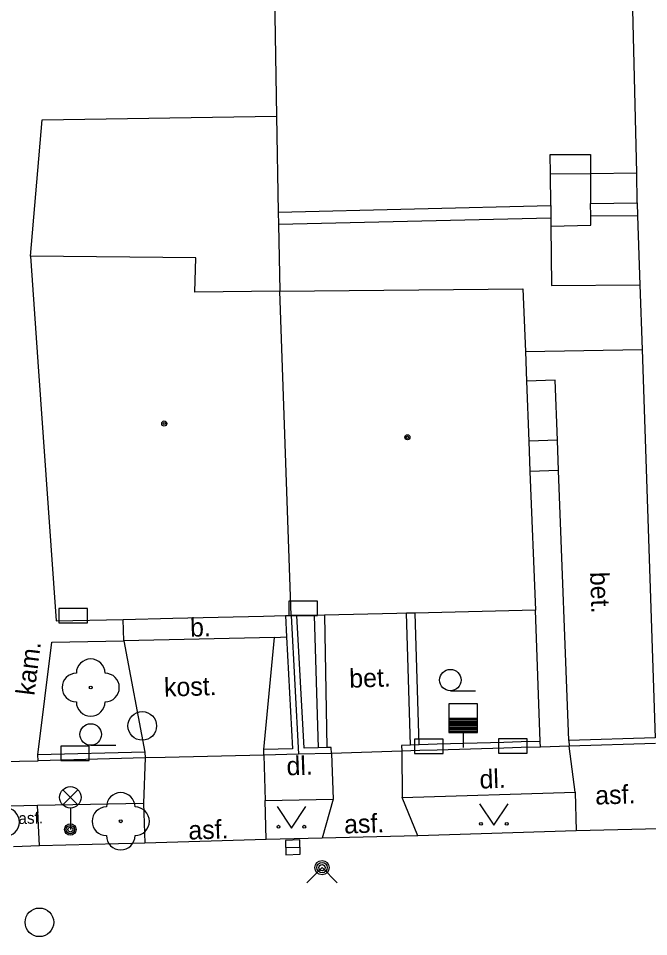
# Model space of a CAD drawing. Extents: x -595546 to -593986, y -1160845 to -1159202.
# Drawn here: x -595096.78 to -595074.76, y -1160780.82 to -1160748.75 of the extents above; entities that cross this region are included whole.
import ezdxf

# ---------------------------------------------------------------- set-up
doc = ezdxf.new("R2010")
doc.units = 0
for name, color, linetype in [('DOP - kresba z DSPS bez souradnic', 7, 'Continuous'), ('DOP - rozhrani ploch obecne', 7, 'Continuous'), ('Level 22', 7, 'Continuous'), ('Level 24', 7, 'Continuous'), ('Level 27', 7, 'Continuous'), ('Level 28', 7, 'Continuous'), ('Level 31', 7, 'Continuous'), ('Level 33', 7, 'Continuous'), ('Level 36', 7, 'Continuous'), ('Level 39', 7, 'Continuous'), ('Specificka linie pasportu komunikaci', 7, 'Continuous'), ('TM - budovy zdene_ betonove - VP', 7, 'Continuous'), ('TM - chodniky - VP', 7, 'Continuous'), ('TM - komunikace - VP', 7, 'Continuous'), ('TM - letecke snimky - pomocna linie', 7, 'Continuous'), ('TM - plot drateny_ kovovy - VP', 7, 'Continuous'), ('TM - podezdivka plotu - VP', 7, 'Continuous'), ('TM - popis povrchu', 7, 'Continuous'), ('TM - rozhrani mezi zpev. plochami mezi sebou - VP', 7, 'Continuous'), ('TM - rozhrani ploch obecne - VP', 7, 'Continuous'), ('TM - vjezd na pozemek', 7, 'Continuous'), ('TM - zed operna - VP', 7, 'Continuous')]:
    doc.layers.add(name, color=color, linetype=linetype)

msp = doc.modelspace()

# ---------------------------------------------------------------- linework, layer by layer
at = {"layer": 'DOP - kresba z DSPS bez souradnic'}
for points in [[(-595078.18, -1160755.29), (-595078.18, -1160755.72)], [(-595076.78, -1160755.66), (-595076.79, -1160755.22)], [(-595075.15, -1160755.65), (-595076.78, -1160755.66)], [(-595076.78, -1160755.97), (-595076.78, -1160755.66)], [(-595087.69, -1160755.94), (-595078.18, -1160755.72)], [(-595078.18, -1160755.72), (-595078.18, -1160756.01)], [(-595078.18, -1160756.01), (-595076.78, -1160755.97)]]:
    msp.add_lwpolyline(points, dxfattribs=at)
at = {"layer": 'DOP - rozhrani ploch obecne'}
for points in [[(-595088.03, -1160735.99), (-595087.76, -1160752.17)], [(-595075.18, -1160754.15), (-595075.54, -1160739.39)], [(-595087.76, -1160752.17), (-595087.7, -1160755.52)], [(-595078.2, -1160753.51), (-595076.8, -1160753.5)], [(-595078.19, -1160754.18), (-595078.2, -1160753.51)], [(-595076.8, -1160753.5), (-595076.8, -1160754.17)], [(-595078.18, -1160755.29), (-595078.19, -1160754.18)], [(-595076.8, -1160754.17), (-595076.79, -1160755.22)], [(-595075.16, -1160755.19), (-595075.18, -1160754.15)], [(-595087.7, -1160755.52), (-595078.18, -1160755.29)], [(-595076.79, -1160755.22), (-595075.16, -1160755.19)], [(-595075.16, -1160755.19), (-595075.15, -1160755.65)], [(-595087.7, -1160755.52), (-595087.69, -1160755.94)], [(-595075.15, -1160755.65), (-595075.07, -1160758.06)], [(-595087.69, -1160755.94), (-595087.64, -1160758.28)], [(-595075.07, -1160758.06), (-595074.99, -1160760.31)]]:
    msp.add_lwpolyline(points, dxfattribs=at)
at = {"layer": 'Level 22'}
for centre in [(-595094.25, -1160772.12), (-595093.2, -1160776.79)]:
    msp.add_circle(centre, 0.05, dxfattribs=at)
for centre, start, end in [((-595094.25, -1160771.62), 0, 180), ((-595094.75, -1160772.12), 90, 270), ((-595093.75, -1160772.12), 270, 90), ((-595094.25, -1160772.62), 180, 0), ((-595093.2, -1160776.29), 0, 180), ((-595097.24, -1160776.82), 270, 90), ((-595093.7, -1160776.79), 90, 270), ((-595092.7, -1160776.79), 270, 90), ((-595093.2, -1160777.29), 180, 0)]:
    msp.add_arc(centre, 0.5, start, end, dxfattribs=at)
at = {"layer": 'Level 24'}
for points in [[(-595087.327, -1160769.608), (-595086.327, -1160769.608), (-595086.327, -1160769.108), (-595087.327, -1160769.108)], [(-595095.367, -1160769.858), (-595094.367, -1160769.858), (-595094.367, -1160769.358), (-595095.367, -1160769.358)], [(-595082.938, -1160774.429), (-595081.938, -1160774.429), (-595081.938, -1160773.929), (-595082.938, -1160773.929)], [(-595080.007, -1160774.408), (-595079.007, -1160774.408), (-595079.007, -1160773.908), (-595080.007, -1160773.908)], [(-595095.298, -1160774.669), (-595094.298, -1160774.669), (-595094.298, -1160774.169), (-595095.298, -1160774.169)]]:
    msp.add_lwpolyline(points, close=True, dxfattribs=at)
at = {"layer": 'Level 27'}
msp.add_line((-595087.44, -1160777.71), (-595086.94, -1160777.69), dxfattribs=at)
msp.add_lwpolyline([(-595087.43, -1160777.96), (-595086.93, -1160777.94), (-595086.95, -1160777.44), (-595087.45, -1160777.46)], close=True, dxfattribs=at)
for centre in [(-595092.45, -1160773.46), (-595096.04, -1160780.32)]:
    msp.add_circle(centre, 0.5, dxfattribs=at)
at = {"layer": 'Level 28'}
for p, q in [((-595081.74, -1160773.19), (-595080.74, -1160773.19)), ((-595081.74, -1160773.24), (-595080.74, -1160773.24)), ((-595081.74, -1160773.29), (-595080.74, -1160773.29)), ((-595081.74, -1160773.34), (-595080.74, -1160773.34)), ((-595081.74, -1160773.39), (-595080.74, -1160773.39)), ((-595081.74, -1160773.44), (-595080.74, -1160773.44)), ((-595081.74, -1160773.49), (-595080.74, -1160773.49)), ((-595081.74, -1160773.54), (-595080.74, -1160773.54)), ((-595081.74, -1160773.59), (-595080.74, -1160773.59)), ((-595081.74, -1160773.64), (-595080.74, -1160773.64)), ((-595081.24, -1160773.69), (-595081.24, -1160774.22))]:
    msp.add_line(p, q, dxfattribs=at)
msp.add_lwpolyline([(-595081.74, -1160773.69), (-595080.74, -1160773.69), (-595080.74, -1160772.69), (-595081.74, -1160772.69)], close=True, dxfattribs=at)
at = {"layer": 'Level 31'}
msp.add_lwpolyline([(-595086.7, -1160778.94), (-595086.17, -1160778.41), (-595085.64, -1160778.94)], dxfattribs=at)
for radius in [0.25, 0.18, 0.11]:
    msp.add_circle((-595086.17, -1160778.41), radius, dxfattribs=at)
at = {"layer": 'Level 33'}
for p, q in [((-595095.225, -1160776.22), (-595094.695, -1160775.69)), ((-595095.225, -1160775.69), (-595094.695, -1160776.22)), ((-595094.96, -1160776.33), (-595094.96, -1160777.08))]:
    msp.add_line(p, q, dxfattribs=at)
for centre, radius in [((-595094.96, -1160775.955), 0.375), ((-595094.96, -1160777.08), 0.2), ((-595094.96, -1160777.08), 0.145), ((-595094.96, -1160777.08), 0.0876)]:
    msp.add_circle(centre, radius, dxfattribs=at)
at = {"layer": 'Level 36'}
for p, q in [((-595081.69, -1160772.235), (-595080.815, -1160772.235)), ((-595094.25, -1160774.135), (-595093.375, -1160774.135))]:
    msp.add_line(p, q, dxfattribs=at)
for points in [[(-595080.67, -1160776.18), (-595080.17, -1160776.93), (-595079.67, -1160776.18)], [(-595087.74, -1160776.28), (-595087.24, -1160777.03), (-595086.74, -1160776.28)]]:
    msp.add_lwpolyline(points, dxfattribs=at)
for centre, radius in [((-595081.69, -1160771.86), 0.375), ((-595094.25, -1160773.76), 0.375), ((-595080.62, -1160776.88), 0.05), ((-595079.721, -1160776.88), 0.05), ((-595087.69, -1160776.98), 0.05), ((-595086.791, -1160776.98), 0.05)]:
    msp.add_circle(centre, radius, dxfattribs=at)
at = {"layer": 'Level 39'}
for centre, radius in [((-595091.68, -1160762.9), 0.09), ((-595091.68, -1160762.9), 0.0398), ((-595083.19, -1160763.38), 0.09), ((-595083.19, -1160763.38), 0.0398)]:
    msp.add_circle(centre, radius, dxfattribs=at)
at = {"layer": 'Specificka linie pasportu komunikaci'}
msp.add_lwpolyline([(-595079.07, -1160760.39), (-595074.99, -1160760.31)], dxfattribs=at)
at = {"layer": 'TM - budovy zdene_ betonove - VP'}
for points in [[(-595090.58, -1160757.11), (-595096.35, -1160757.06)], [(-595096.35, -1160757.06), (-595096.09, -1160760.74)], [(-595090.61, -1160758.31), (-595090.58, -1160757.11)], [(-595087.64, -1160758.28), (-595079.16, -1160758.2)], [(-595079.16, -1160758.2), (-595079.07, -1160760.39)], [(-595087.64, -1160758.28), (-595090.61, -1160758.31)], [(-595087.25, -1160769.61), (-595087.64, -1160758.28)], [(-595079.07, -1160760.39), (-595079.03, -1160761.42)], [(-595096.09, -1160760.74), (-595095.45, -1160769.79)], [(-595079.03, -1160761.42), (-595078.95, -1160763.52)], [(-595078.95, -1160763.52), (-595078.91, -1160764.58)], [(-595078.91, -1160764.58), (-595078.72, -1160769.42)], [(-595078.72, -1160769.42), (-595082.92, -1160769.52)], [(-595095.45, -1160769.79), (-595093.12, -1160769.74)], [(-595093.12, -1160769.74), (-595091.38, -1160769.7), (-595088.21, -1160769.63), (-595087.45, -1160769.61)], [(-595087.45, -1160769.61), (-595087.25, -1160769.61)], [(-595087.05, -1160769.61), (-595087.25, -1160769.61)], [(-595086.44, -1160769.6), (-595087.05, -1160769.61)], [(-595086.09, -1160769.59), (-595086.44, -1160769.6)], [(-595083.22, -1160769.52), (-595083.56, -1160769.53), (-595086.09, -1160769.59)], [(-595082.92, -1160769.52), (-595083.22, -1160769.52)]]:
    msp.add_lwpolyline(points, dxfattribs=at)
at = {"layer": 'TM - chodniky - VP'}
for points in [[(-595083.37, -1160775.96), (-595077.33, -1160775.78)], [(-595077.33, -1160775.78), (-595077.29, -1160777.13)], [(-595096.11, -1160776.23), (-595092.4, -1160776.16)], [(-595092.4, -1160776.16), (-595092.36, -1160777.55)], [(-595088.16, -1160776.07), (-595085.78, -1160776.02)], [(-595088.12, -1160777.43), (-595088.16, -1160776.07)], [(-595085.78, -1160776.02), (-595086.17, -1160777.38)], [(-595082.82, -1160777.3), (-595083.37, -1160775.96)], [(-595096.04, -1160777.65), (-595096.11, -1160776.23)]]:
    msp.add_lwpolyline(points, dxfattribs=at)
at = {"layer": 'TM - komunikace - VP'}
for points in [[(-595077.29, -1160777.13), (-595082.82, -1160777.3)], [(-595074.38, -1160777.05), (-595077.29, -1160777.13)], [(-595088.12, -1160777.43), (-595092.36, -1160777.55)], [(-595086.17, -1160777.38), (-595088.12, -1160777.43)], [(-595082.82, -1160777.3), (-595086.17, -1160777.38)], [(-595096.04, -1160777.65), (-595096.95, -1160777.68)], [(-595092.36, -1160777.55), (-595096.04, -1160777.65)]]:
    msp.add_lwpolyline(points, dxfattribs=at)
at = {"layer": 'TM - letecke snimky - pomocna linie'}
for points in [[(-595096.35, -1160757.06), (-595095.95, -1160752.29), (-595087.76, -1160752.17)], [(-595078.19, -1160754.18), (-595076.8, -1160754.17)], [(-595076.8, -1160754.17), (-595075.18, -1160754.15)], [(-595078.18, -1160756.01), (-595078.16, -1160758.08), (-595075.07, -1160758.06)]]:
    msp.add_lwpolyline(points, dxfattribs=at)
at = {"layer": 'TM - plot drateny_ kovovy - VP'}
for points in [[(-595074.99, -1160760.31), (-595074.54, -1160773.88)], [(-595087.45, -1160769.61), (-595087.41, -1160770.35)], [(-595086.3, -1160774.23), (-595086.8, -1160774.24), (-595087.05, -1160769.61)], [(-595087.41, -1160770.35), (-595087.2, -1160774.26), (-595088.2, -1160774.28)], [(-595074.54, -1160773.88), (-595077.55, -1160773.97)], [(-595086, -1160774.22), (-595086.3, -1160774.23)], [(-595085.85, -1160774.22), (-595086, -1160774.22)], [(-595083.08, -1160774.13), (-595083.39, -1160774.14)], [(-595082.78, -1160774.12), (-595083.08, -1160774.13)], [(-595082.15, -1160774.1), (-595082.78, -1160774.12)], [(-595079.82, -1160774.04), (-595082.15, -1160774.1)], [(-595079.22, -1160774.02), (-595079.82, -1160774.04)], [(-595078.55, -1160774), (-595079.22, -1160774.02)], [(-595092.36, -1160774.38), (-595096.09, -1160774.47)]]:
    msp.add_lwpolyline(points, dxfattribs=at)
at = {"layer": 'TM - podezdivka plotu - VP'}
for points in [[(-595087.25, -1160769.61), (-595086.99, -1160774.45)], [(-595086.09, -1160769.59), (-595086, -1160774.22)], [(-595083.08, -1160774.13), (-595083.22, -1160769.52)], [(-595077.55, -1160773.97), (-595077.54, -1160774.17)], [(-595088.2, -1160774.48), (-595088.2, -1160774.28)], [(-595085.84, -1160774.42), (-595085.85, -1160774.22)], [(-595083.39, -1160774.14), (-595083.38, -1160774.34)], [(-595079.82, -1160774.24), (-595082.15, -1160774.31)], [(-595079.22, -1160774.22), (-595079.82, -1160774.24)], [(-595078.54, -1160774.2), (-595079.22, -1160774.22)], [(-595078.54, -1160774.2), (-595078.55, -1160774)], [(-595074.53, -1160774.08), (-595077.54, -1160774.17)], [(-595096.08, -1160774.68), (-595096.09, -1160774.47)], [(-595092.35, -1160774.58), (-595096.08, -1160774.68)], [(-595092.36, -1160774.38), (-595092.35, -1160774.58)], [(-595088.2, -1160774.48), (-595091.65, -1160774.56), (-595092.35, -1160774.58)], [(-595086.99, -1160774.45), (-595088.2, -1160774.48)], [(-595085.84, -1160774.42), (-595086.99, -1160774.45)], [(-595082.75, -1160774.32), (-595083.38, -1160774.34)], [(-595082.15, -1160774.31), (-595082.75, -1160774.32)]]:
    msp.add_lwpolyline(points, dxfattribs=at)
at = {"layer": 'TM - rozhrani mezi zpev. plochami mezi sebou - VP'}
for points in [[(-595093.09, -1160770.49), (-595093.12, -1160769.74)], [(-595087.83, -1160770.37), (-595093.09, -1160770.49)], [(-595077.33, -1160775.78), (-595077.54, -1160774.17)], [(-595092.35, -1160774.58), (-595092.4, -1160776.16)], [(-595088.2, -1160774.48), (-595088.16, -1160776.07)], [(-595085.84, -1160774.42), (-595085.78, -1160776.02)], [(-595083.38, -1160774.34), (-595083.37, -1160775.96)], [(-595097.06, -1160776.25), (-595096.11, -1160776.23)]]:
    msp.add_lwpolyline(points, dxfattribs=at)
at = {"layer": 'TM - rozhrani ploch obecne - VP'}
for points in [[(-595077.95, -1160763.48), (-595078.03, -1160761.38), (-595079.03, -1160761.42)], [(-595077.95, -1160763.48), (-595078.95, -1160763.52)], [(-595077.91, -1160764.54), (-595077.95, -1160763.48)], [(-595077.91, -1160764.54), (-595078.91, -1160764.58)], [(-595077.55, -1160773.97), (-595077.91, -1160764.54)], [(-595078.55, -1160774), (-595078.72, -1160769.42)], [(-595088.2, -1160774.28), (-595087.83, -1160770.37)], [(-595087.83, -1160770.37), (-595087.41, -1160770.35)], [(-595096.09, -1160774.47), (-595095.61, -1160770.54), (-595093.09, -1160770.49)], [(-595093.09, -1160770.49), (-595092.36, -1160774.38)]]:
    msp.add_lwpolyline(points, dxfattribs=at)
at = {"layer": 'TM - vjezd na pozemek'}
for points in [[(-595077.54, -1160774.17), (-595078.54, -1160774.2)], [(-595083.38, -1160774.34), (-595085.84, -1160774.42)], [(-595097.39, -1160774.7), (-595096.08, -1160774.68)]]:
    msp.add_lwpolyline(points, dxfattribs=at)
at = {"layer": 'TM - zed operna - VP'}
for points in [[(-595086.44, -1160769.6), (-595086.3, -1160774.23)], [(-595082.78, -1160774.12), (-595082.92, -1160769.52)]]:
    msp.add_lwpolyline(points, dxfattribs=at)

# ---------------------------------------------------------------- texts
at = {"layer": 'TM - popis povrchu'}
for s, height, rotation, p in [('bet.', 0.65, 271.9572, (-595076.81, -1160768.09)), ('b.', 0.65, 1.7964, (-595090.77, -1160770.35)), ('kam.', 0.65, 82.8897, (-595096.22, -1160772.42)), ('bet.', 0.65, 1.9572, (-595085.21, -1160772.13)), ('kost.', 0.65, 1.7964, (-595091.68, -1160772.44)), ('dl.', 0.65, 1.9572, (-595087.4, -1160775.19)), ('dl.', 0.65, 1.9572, (-595080.66, -1160775.65)), ('asf.', 0.65, 1.9572, (-595076.62, -1160776.21)), ('asf.', 0.4, 1.6925, (-595096.77, -1160776.89)), ('asf.', 0.65, 1.9572, (-595085.39, -1160777.22)), ('asf.', 0.65, 1.7964, (-595090.83, -1160777.43))]:
    msp.add_text(s, height=height, rotation=rotation, dxfattribs=at).set_placement(p)

doc.saveas('drawing.dxf')
